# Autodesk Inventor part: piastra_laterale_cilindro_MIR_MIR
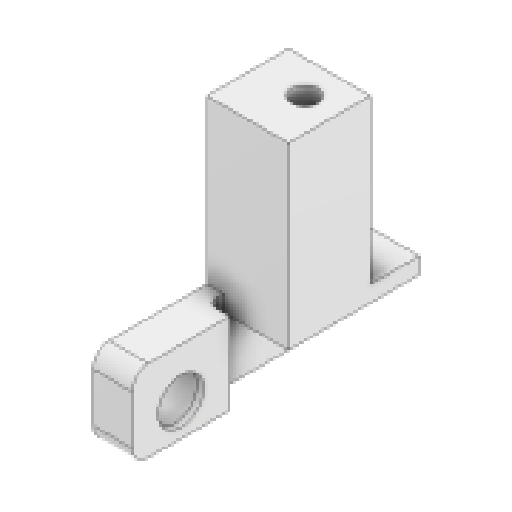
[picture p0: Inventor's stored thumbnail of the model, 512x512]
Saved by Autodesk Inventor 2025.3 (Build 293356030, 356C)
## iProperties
Created: 2025-09
Part Number: piastra_laterale_cilindro_MIR_MIR
Material: Plastica ABS
Document SubType Name: Modeling
Designer: R5800u
Density: 1.06 g/cm^3
Appearance: Liscia - Bianco
Author: R5800u
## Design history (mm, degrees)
derived "piastra_laterale_cilindro_MIR.ipt"
  sketch "Schizzo1"
    geometry: L1 (-2.5, 10)-(2.5, 10) reference; L2 (2.5, 10)-(2.5, -10) reference; L3 (2.5, -10)-(-2.5, -10) reference; L4 (-2.5, -10)-(-2.5, 10) reference; L5 (-2.5, 10)-(2.5, -10) reference; L6 (2.5, 10)-(-2.5, -10) reference; 1 further point
  sketch "Schizzo2"
    geometry: L1 (50, 20)-(0, 20) reference; L2 (0, 0)-(25, 0) reference; L3 (25, 0)-(25, 20) reference; L4 (25, 20)-(0, 20) reference; L5 (0, 20)-(0, 0) reference; L6 (30, 1)-(30, 6.7) reference; L7 (25, 0)-(30, 0) reference; L8 (30, 0)-(30, 20) reference; L9 (30, 20)-(25, 20) reference; L10 (25, 20)-(25, 0) reference; 1 further point
  sketch "Schizzo3"
    geometry: C1 r 4 at (-10, 10) reference; C2 r 8 at (-10, 10) reference; 1 further point
  sketch "Schizzo4"
    geometry: L1 (-2.5, -10)-(2.5, -10) reference; L2 (2.5, -10)-(2.5, 10) reference; L3 (2.5, 10)-(-2.5, 10) reference; L4 (-2.5, 10)-(-2.5, -10) reference; 1 further point
feature "Solido1::piastra_laterale_cilindro_MIR.ipt"
tag "Lavorazione contrassegno1"
node "Solido1"
